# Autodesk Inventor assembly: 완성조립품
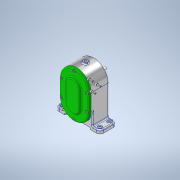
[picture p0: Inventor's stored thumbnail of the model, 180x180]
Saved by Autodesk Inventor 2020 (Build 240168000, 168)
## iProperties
Created: 2021-05
Part Number: 완성조립품
Document SubType Name: Assembly
Designer: Owner
Author: Owner
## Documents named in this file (15)
- C:\Users\Owner\Desktop\710507V1009\완성조립품.iam
- C:\Users\Owner\Desktop\710507V1009\본체.ipt
- C:\Users\Owner\Desktop\710507V1009\베어링 6001.ipt
- 베어링 6001.ipt
- C:\Users\Owner\Desktop\710507V1009\칼라.ipt
- C:\Users\Owner\Desktop\710507V1009\스퍼기어 A.ipt
- C:\Users\Owner\Desktop\710507V1009\스퍼기어 B.ipt
- C:\Users\Owner\Desktop\710507V1009\축 A.ipt
- C:\Users\Owner\Desktop\710507V1009\베어링 6002.ipt
- 베어링 6002.ipt
- C:\Users\Owner\Desktop\710507V1009\축 B.ipt
- C:\Users\Owner\Desktop\710507V1009\키 5 x 5 x 12.ipt
- C:\Users\Owner\Desktop\710507V1009\키 4 x 4 x 12.ipt
- C:\Users\Owner\Desktop\710507V1009\커버 A.ipt
- C:\Users\Owner\Desktop\710507V1009\볼트 M4.ipt
